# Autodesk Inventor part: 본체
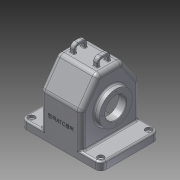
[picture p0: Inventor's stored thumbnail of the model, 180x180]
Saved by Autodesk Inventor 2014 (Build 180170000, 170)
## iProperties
Created: 2016-12
Part Number: 본체
Material: 알루미늄 6061
Document SubType Name: Modeling
Designer: USER
Density: 2.71 g/cm^3
Appearance: 알루미늄 - 평지
Mass: 1067.57 g
Surface Area: 1139.73 cm^2
Volume: 393.937 cm^3
Author: USER
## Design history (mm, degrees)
sketch "스케치1"
  geometry: L1 (110, 0)-(110, -65); L2 (110, -65)-(0, -65); L3 (0, -65)-(0, 0); L4 (0, 0)-(31.509, 45); L5 (31.509, 45)-(78.491, 45); L6 (78.491, 45)-(110, 0)
  constraints: 12 end point, 2 horizontal alignment, 2 vertical alignment, 1 equal length, 1 parallel, 1 perpendicular
  dimensions: "d0" = 65 distance of L1.start L1.end; "d1" = 35 deg angle of L3 L4; "d2" = 35 deg angle of L1 L6; "d3" = 110 distance between parallel lines of L2 L5; "d4" = 110 distance of L1.end L2.end
extrude "돌출1" new body sketch "스케치1" distance "d5" = 77; taper "d6" = 0 deg
fillet "모깎기1" dims "d7" = 10
node "작업 평면1"
sketch "스케치5"
  geometry: L1 (-40.736, 28.523)-(-2.583, 1.808) reference; L2 (-45, 73.285)-(-45, 36.715) reference; L3 (-2.583, 108.192)-(-40.736, 81.477) reference; L4 (65, 110)-(3.153, 110) reference; L5 (3.153, 0)-(65, 0) reference; L6 (110.135, 5)-(3.153, 5); L7 (0.285, 5.904)-(-37.868, 32.619); L8 (-40, 36.715)-(-40, 73.285); L9 (-37.868, 77.381)-(0.285, 104.096); L10 (3.153, 105)-(110.135, 105); L11 (110.135, 5)-(110.135, 105); A1 r 10 centre (-35, 36.715) between (-45, 36.715) and (-40.736, 28.523) reference; A2 r 10 centre (-35, 73.285) between (-40.736, 81.477) and (-45, 73.285) reference; A3 r 10 centre (3.153, 100) between (3.153, 110) and (-2.583, 108.192) reference; A4 r 10 centre (3.153, 10) between (-2.583, 1.808) and (3.153, 0) reference; A5 r 5 centre (3.153, 10) between (0.285, 5.904) and (3.153, 5); A6 r 5 centre (-35, 36.715) between (-40, 36.715) and (-37.868, 32.619); A7 r 5 centre (-35, 73.285) between (-37.868, 77.381) and (-40, 73.285); A8 r 5 centre (3.153, 100) between (3.153, 105) and (0.285, 104.096); 1 further point
  constraints: 12 end point, 8 point on circle, 4 centre point, 1 perpendicular, 8 other
  dimensions: "d26" = 5 distance between parallel lines of L2 L8; "d29" = 150.13503 distance between parallel lines of L8 L11
extrude "돌출5" cut sketch "스케치5" stored distance "d27" = 67; taper "d28" = 0 deg
node "작업 평면2"
fillet "모깎기2" dims "d8" = 8
sketch "스케치2"
  geometry: L1 (0, 0)-(0, 94) reference; L2 (-8, 102)-(-69, 102) reference; L3 (-8, -8)-(-69, -8) reference; L4 (36.5, -8)-(-113.5, -8); L5 (-113.5, -8)-(-113.5, 102); L6 (-113.5, 102)-(36.5, 102); L7 (36.5, 102)-(36.5, -8); 7 further points
  constraints: 8 end point, 6 midpoint, 2 coincident, 2 parallel, 1 horizontal, 1 horizontal alignment, 1 perpendicular
  dimensions: "d10" = 110 distance of L6.end L4.start; "d11" = 150 distance of L5.end L6.end
extrude "돌출2" join sketch "스케치2" distance "d12" = 15; taper "d13" = 0 deg
fillet "모깎기3" dims "d14" = 10
fillet "모깎기4" dims "d15" = 3
fillet "모깎기5" dims "d16" = 3
sketch "스케치3"
  geometry: L1 (-37, 36.715)-(-37, 73.285) reference; L2 (80, 100)-(80, 10) reference; C1 r 31 at (15, 55); 2 further points
  constraints: 1 centre point, 1 horizontal alignment, 1 midpoint
  dimensions: "d17" = 62 diameter of C1; "d18" = 65 distance from line of L2 C1.centre
extrude "돌출3" join sketch "스케치3" distance "d19" = 10; taper "d20" = 0 deg
sketch "스케치4"
  geometry: L1 (37, 73.285)-(37, 36.715) reference; L2 (-80, 10)-(-80, 100) reference; C1 r 37.5 at (-15, 55); 2 further points
  constraints: 1 centre point, 1 horizontal alignment, 1 midpoint
  dimensions: "d21" = 75 diameter of C1; "d22" = 65 distance from line of C1.centre L2
extrude "돌출4" join sketch "스케치4" distance "d23" = 5; taper "d24" = 0 deg
fillet "모깎기6" dims "d25" = 3
sketch "스케치6"
  geometry: L1 (65, 5)-(3.153, 5) reference; L2 (3.153, 105)-(65, 105) reference; L3 (65, 5)-(87.352, 5); L4 (87.352, 5)-(87.352, 105); L5 (87.352, 105)-(65, 105); L6 (65, 5)-(65, 105); 1 further point
  constraints: 8 end point, 2 parallel, 2 perpendicular
  dimensions: "d30" = 22.35191 distance between parallel lines of L4 L6
extrude "돌출6" cut sketch "스케치6" stored distance "d31" = 67; taper "d32" = 0 deg
fillet "모깎기7" dims "d33" = 3
node "작업 평면4"
  node "작업 평면3"
sketch "스케치7"
  geometry: L1 (82.583, 98.192)-(120.736, 71.477) reference; L2 (120.736, 18.523)-(82.583, -8.192) reference; L3 (125, 57.5)-(140, 57.5); L4 (140, 57.5)-(140, 32.5); L5 (140, 32.5)-(125, 32.5); L6 (125, 52.5)-(135, 52.5); L7 (135, 52.5)-(135, 37.5); L8 (135, 37.5)-(125, 37.5); L9 (125, 63.285)-(125, 26.715) reference; L10 (125, 57.5)-(125, 52.5); L11 (125, 37.5)-(125, 32.5); A1 r 10 centre (115, 63.285) between (125, 63.285) and (120.736, 71.477) reference; A2 r 10 centre (115, 26.715) between (120.736, 18.523) and (125, 26.715) reference; 4 further points
  constraints: 16 end point, 4 vertical alignment, 3 midpoint, 2 collinear, 2 horizontal, 2 horizontal alignment, 2 parallel, 2 perpendicular
  dimensions: "d36" = 25 distance between parallel lines of L5 L3; "d37" = 15 distance between parallel lines of L8 L6; "d38" = 15 distance of L4.end L5.end; "d39" = 10 distance between parallel lines of L9 L7
extrude "돌출7" join sketch "스케치7" distance "d40" = 8; taper "d41" = 0 deg
fillet "모깎기8" dims "d42" = 8
fillet "모깎기9" dims "d43" = 3
fillet "모깎기10" dims "d44" = 1
fillet "모깎기11" dims "d45" = 1
sketch "스케치8"
  geometry: C1 r 31 at (0, 0) reference; C2 r 20 at (0, 0); 1 further point
  constraints: 1 centre point, 1 coincident
  dimensions: "d46" = 40 diameter of C2
extrude "돌출8" cut sketch "스케치8" stored distance "d47" = 8; taper "d48" = 0 deg
node "작업 평면5"
sketch "스케치9"
  geometry: L1 (-13, -31.847)-(-13, 8.153) reference; L2 (-13, -11.847)-(67.573, -11.847); L3 (-3, 39.3)-(-3, 1.147) reference; L4 (-3, 0)-(-3, -76.847) reference; L5 (11, 8.153)-(11, 15.153); L6 (11, 15.153)-(-3, 29.153); L7 (-3, 8.153)-(11, 8.153); L8 (-3, 8.153)-(-3, 29.153); 1 further point
  constraints: 10 end point, 2 perpendicular, 2 point on line, 1 collinear, 1 horizontal alignment, 1 midpoint, 1 parallel, 1 vertical alignment
  dimensions: "d49" = 40 diameter of L7 L2; "d50" = 54 diameter of L5.end L2; "d51" = 45 deg angle of L5 L6; "d52" = 24 distance between parallel lines of L5 L1
revolve "회전1" sketch "스케치9" stored, may be unused: angle "d53" = 90 deg
sketch "스케치10" dims "d54" = 52
  geometry: C1 r 20 at (0, 0) reference; C2 r 31 at (0, 0) reference; 3 further points
  constraints: 2 horizontal alignment, 1 coincident, 2 other
hole "구멍1" sketch "스케치10" at (-26, 0) diameter "d55" = 2.459; stored, may be unused: countersink angle "d59" = 90 deg, drill point angle "d61" = 118 deg; dims "d56" = 6, "d57" = 4, "d58" = 2, "d60" = 8
sketch "스케치11" dims "d65" = 58
  geometry: C1 r 20 at (0, 0) reference; C2 r 37.5 at (0, 0) reference; 3 further points
  constraints: 2 horizontal alignment, 1 coincident, 2 other
hole "구멍2" sketch "스케치11" at (29, 0) diameter "d66" = 2.459; stored, may be unused: countersink angle "d70" = 90 deg, drill point angle "d72" = 118 deg; dims "d67" = 6, "d68" = 4, "d69" = 2, "d71" = 8
sketch "스케치12"
  geometry: A1 r 7 centre (103.5, 2) between (103.5, -5) and (110.5, 2) reference; A2 r 7 centre (103.5, 92) between (110.5, 92) and (103.5, 99) reference; 3 further points
  constraints: 2 coincident
hole "구멍3" sketch "스케치12" at (103.5, 92), (103.5, 2) diameter "d76" = 5; stored, may be unused: countersink angle "d80" = 90 deg, drill point angle "d82" = 118 deg; dims "d77" = 6, "d78" = 12, "d79" = 5, "d81" = 8
sketch "스케치13"
  geometry: L1 (95.5, -76.847)-(-34.5, -76.847) reference; L2 (-8, 0)-(-8, -58.847) reference; 2 further points
  constraints: 1 other
  dimensions: "d83" = 38.5 distance from line of point (30.5, -31.847) L2; "d84" = 45 distance from line of L1 point (30.5, -31.847)
feature "엠보싱1" sketch "스케치13" dims "d85" = 0.5, "d86" = 0
fillet "모깎기12" dims "d87" = 3
chamfer "모따기1" distance "d88" = 1; stored, may be unused: second distance "d89" = 2, angle "d90" = 45 deg
node "솔리드1"
mirror "대칭1"
pattern_circular "원형 패턴1" dims angle "d63" = 360 deg
pattern_circular "원형 패턴2" dims angle "d74" = 360 deg
mirror "대칭2"
other parameters: "d34" = -75, "d35" = 26
